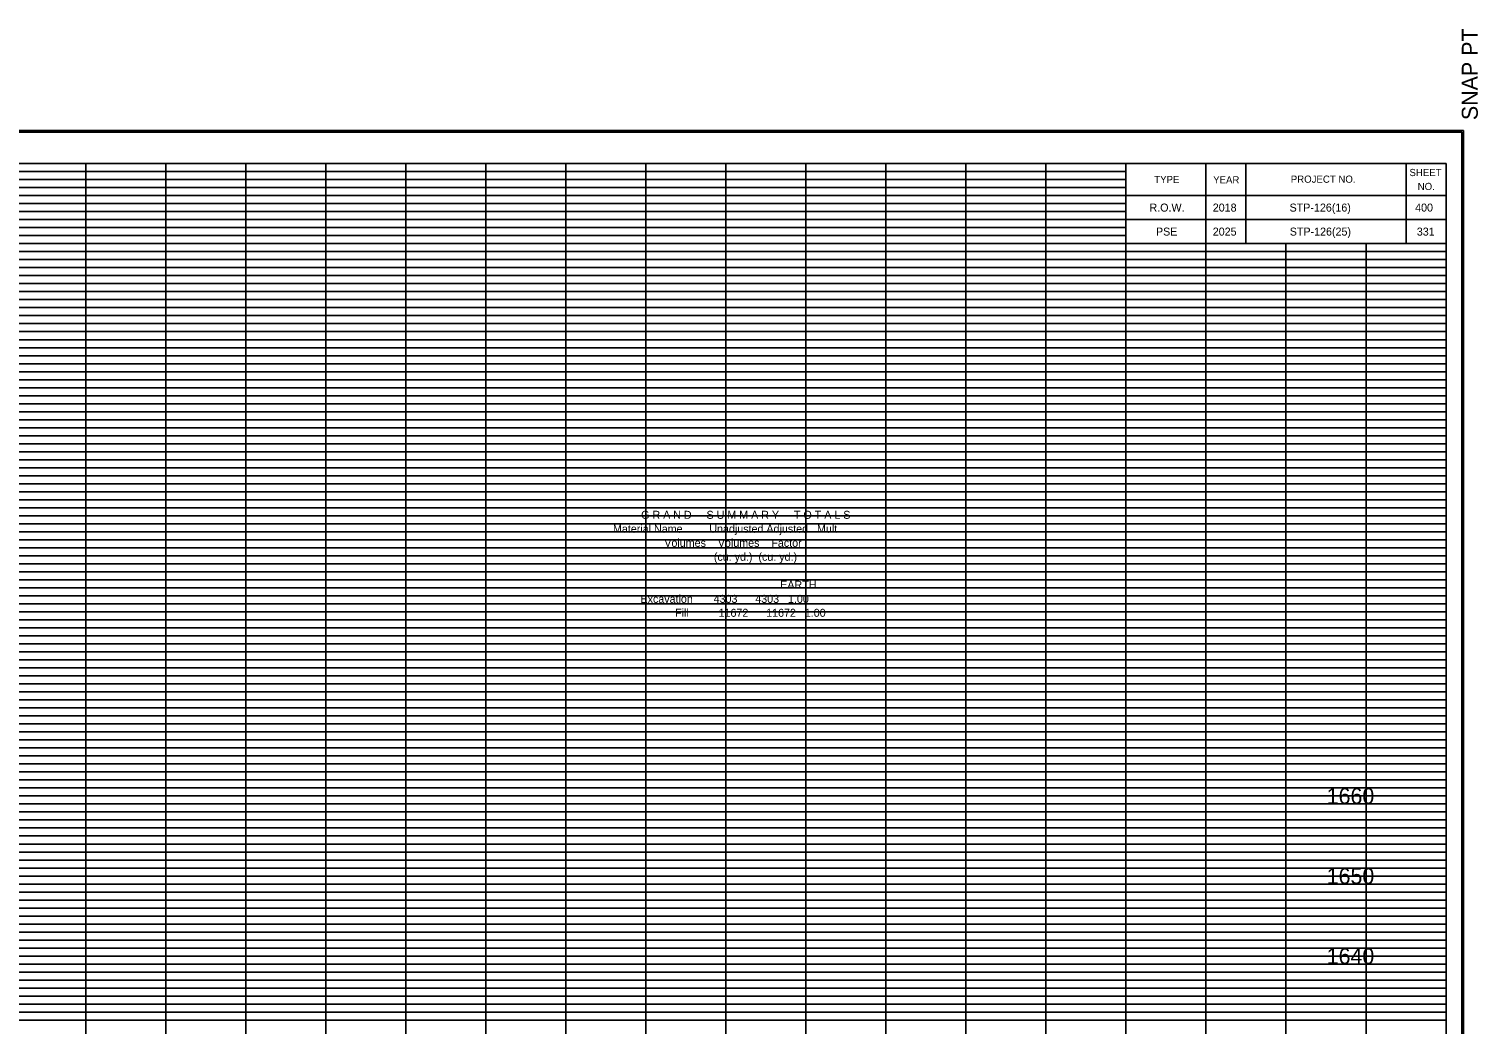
# Model space of a CAD drawing. Extents: x 955 to 1375, y 1248 to 3657.
# Drawn here: x 1142.9 to 1324, y 3532.5 to 3656.8 of the extents above; entities that cross this region are included whole.
import ezdxf

# ---------------------------------------------------------------- set-up
doc = ezdxf.new("R2010")
doc.units = 0
for name, color, linetype in [('DESIGN - SCRATCH - User 1', 7, 'Continuous'), ('DESIGN - SHEET - Corner Text', 7, 'Continuous'), ('DESIGN - SHEET - Light Grid', 7, 'Continuous'), ('DESIGN - SHEET - Linework', 7, 'Continuous'), ('DESIGN - SHEET - Plot Shape', 7, 'Continuous'), ('DESIGN - TYPICAL - Text', 7, 'Continuous'), ('DESIGN - UTILITIES - Cable (Overhead) with Text', 7, 'Continuous')]:
    doc.layers.add(name, color=color, linetype=linetype)

# ---------------------------------------------------------------- blocks, each defined once
blk = doc.blocks.new('XSTSHT')
at = {"layer": 'DESIGN - SCRATCH - User 1'}
for p, q in [((28.5, 20.45), (28.5, 20.45)), ((29.24, 20.45), (29.24, 20.45)), ((30.49, 20.45), (30.49, 20.45)), ((31.74, 20.45), (31.74, 20.45)), ((28.5, 20.15), (28.5, 20.15)), ((29.24, 20.15), (29.24, 20.15)), ((30.49, 20.15), (30.49, 20.15)), ((31.74, 20.15), (31.74, 20.15))]:
    blk.add_line(p, q, dxfattribs=at)
at = {"layer": 'DESIGN - SHEET - Light Grid'}
for p, q in [((8, 20.9), (16, 20.9)), ((16, 20.9), (24, 20.9)), ((24, 20.9), (28, 20.9)), ((8, 20.8), (16, 20.8)), ((8, 20.7), (16, 20.7)), ((16, 20.8), (24, 20.8)), ((16, 20.7), (24, 20.7)), ((24, 20.8), (28, 20.8)), ((24, 20.7), (28, 20.7)), ((8, 20.6), (16, 20.6)), ((8, 20.5), (16, 20.5)), ((16, 20.6), (24, 20.6)), ((16, 20.5), (24, 20.5)), ((24, 20.6), (28, 20.6)), ((24, 20.5), (28, 20.5)), ((8, 20.4), (16, 20.4)), ((8, 20.3), (16, 20.3)), ((16, 20.4), (24, 20.4)), ((16, 20.3), (24, 20.3)), ((24, 20.4), (28, 20.4)), ((24, 20.3), (28, 20.3)), ((8, 20.2), (16, 20.2)), ((16, 20.2), (24, 20.2)), ((24, 20.2), (28, 20.2)), ((8, 20.1), (16, 20.1)), ((16, 20.1), (24, 20.1)), ((24, 20.1), (28, 20.1)), ((8, 19.9), (16, 19.9)), ((8, 19.8), (16, 19.8)), ((16, 19.9), (24, 19.9)), ((16, 19.8), (24, 19.8)), ((24, 19.9), (32, 19.9)), ((24, 19.8), (32, 19.8)), ((8, 19.7), (16, 19.7)), ((8, 19.6), (16, 19.6)), ((16, 19.7), (24, 19.7)), ((16, 19.6), (24, 19.6)), ((24, 19.7), (32, 19.7)), ((24, 19.6), (32, 19.6)), ((8, 19.5), (16, 19.5)), ((8, 19.4), (16, 19.4)), ((16, 19.5), (24, 19.5)), ((16, 19.4), (24, 19.4)), ((24, 19.5), (32, 19.5)), ((24, 19.4), (32, 19.4)), ((8, 19.3), (16, 19.3)), ((8, 19.2), (16, 19.2)), ((16, 19.3), (24, 19.3)), ((16, 19.2), (24, 19.2)), ((24, 19.3), (32, 19.3)), ((24, 19.2), (32, 19.2)), ((8, 19.1), (16, 19.1)), ((16, 19.1), (24, 19.1)), ((24, 19.1), (32, 19.1)), ((8, 18.9), (16, 18.9)), ((16, 18.9), (24, 18.9)), ((24, 18.9), (32, 18.9)), ((8, 18.8), (16, 18.8)), ((8, 18.7), (16, 18.7)), ((16, 18.8), (24, 18.8)), ((16, 18.7), (24, 18.7)), ((24, 18.8), (32, 18.8)), ((24, 18.7), (32, 18.7)), ((8, 18.6), (16, 18.6)), ((8, 18.5), (16, 18.5)), ((16, 18.6), (24, 18.6)), ((16, 18.5), (24, 18.5)), ((24, 18.6), (32, 18.6)), ((24, 18.5), (32, 18.5)), ((8, 18.4), (16, 18.4)), ((8, 18.3), (16, 18.3)), ((16, 18.4), (24, 18.4)), ((16, 18.3), (24, 18.3)), ((24, 18.4), (32, 18.4)), ((24, 18.3), (32, 18.3)), ((8, 18.2), (16, 18.2)), ((16, 18.2), (24, 18.2)), ((24, 18.2), (32, 18.2)), ((8, 18.1), (16, 18.1)), ((16, 18.1), (24, 18.1)), ((24, 18.1), (32, 18.1)), ((8, 17.9), (16, 17.9)), ((8, 17.8), (16, 17.8)), ((16, 17.9), (24, 17.9)), ((16, 17.8), (24, 17.8)), ((24, 17.9), (32, 17.9)), ((24, 17.8), (32, 17.8)), ((8, 17.7), (16, 17.7)), ((8, 17.6), (16, 17.6)), ((16, 17.7), (24, 17.7)), ((16, 17.6), (24, 17.6)), ((24, 17.7), (32, 17.7)), ((24, 17.6), (32, 17.6)), ((8, 17.5), (16, 17.5)), ((8, 17.4), (16, 17.4)), ((16, 17.5), (24, 17.5)), ((16, 17.4), (24, 17.4)), ((24, 17.5), (32, 17.5)), ((24, 17.4), (32, 17.4)), ((8, 17.3), (16, 17.3)), ((16, 17.3), (24, 17.3)), ((24, 17.3), (32, 17.3)), ((8, 17.2), (16, 17.2)), ((8, 17.1), (16, 17.1)), ((16, 17.2), (24, 17.2)), ((16, 17.1), (24, 17.1)), ((24, 17.2), (32, 17.2)), ((24, 17.1), (32, 17.1)), ((8, 16.9), (16, 16.9)), ((16, 16.9), (24, 16.9)), ((24, 16.9), (32, 16.9)), ((8, 16.8), (16, 16.8)), ((8, 16.7), (16, 16.7)), ((16, 16.8), (24, 16.8)), ((16, 16.7), (24, 16.7)), ((24, 16.8), (32, 16.8)), ((24, 16.7), (32, 16.7)), ((8, 16.6), (16, 16.6)), ((8, 16.5), (16, 16.5)), ((16, 16.6), (24, 16.6)), ((16, 16.5), (24, 16.5)), ((24, 16.6), (32, 16.6)), ((24, 16.5), (32, 16.5)), ((8, 16.4), (16, 16.4)), ((8, 16.3), (16, 16.3)), ((16, 16.4), (24, 16.4)), ((16, 16.3), (24, 16.3)), ((24, 16.4), (32, 16.4)), ((24, 16.3), (32, 16.3)), ((8, 16.2), (16, 16.2)), ((16, 16.2), (24, 16.2)), ((24, 16.2), (32, 16.2)), ((8, 16.1), (16, 16.1)), ((16, 16.1), (24, 16.1)), ((24, 16.1), (32, 16.1)), ((8, 15.9), (16, 15.9)), ((8, 15.8), (16, 15.8)), ((16, 15.9), (24, 15.9)), ((16, 15.8), (24, 15.8)), ((24, 15.9), (32, 15.9)), ((24, 15.8), (32, 15.8)), ((8, 15.7), (16, 15.7)), ((8, 15.6), (16, 15.6)), ((16, 15.7), (24, 15.7)), ((16, 15.6), (24, 15.6)), ((24, 15.7), (32, 15.7)), ((24, 15.6), (32, 15.6)), ((8, 15.5), (16, 15.5)), ((8, 15.4), (16, 15.4)), ((16, 15.5), (24, 15.5)), ((16, 15.4), (24, 15.4)), ((24, 15.5), (32, 15.5)), ((24, 15.4), (32, 15.4)), ((8, 15.3), (16, 15.3)), ((16, 15.3), (24, 15.3)), ((24, 15.3), (32, 15.3)), ((8, 15.2), (16, 15.2)), ((8, 15.1), (16, 15.1)), ((16, 15.2), (24, 15.2)), ((16, 15.1), (24, 15.1)), ((24, 15.2), (32, 15.2)), ((24, 15.1), (32, 15.1)), ((8, 14.9), (16, 14.9)), ((16, 14.9), (24, 14.9)), ((24, 14.9), (32, 14.9)), ((8, 14.8), (16, 14.8)), ((8, 14.7), (16, 14.7)), ((16, 14.8), (24, 14.8)), ((16, 14.7), (24, 14.7)), ((24, 14.8), (32, 14.8)), ((24, 14.7), (32, 14.7)), ((8, 14.6), (16, 14.6)), ((8, 14.5), (16, 14.5)), ((16, 14.6), (24, 14.6)), ((16, 14.5), (24, 14.5)), ((24, 14.6), (32, 14.6)), ((24, 14.5), (32, 14.5)), ((8, 14.4), (16, 14.4)), ((16, 14.4), (24, 14.4)), ((24, 14.4), (32, 14.4)), ((8, 14.3), (16, 14.3)), ((8, 14.2), (16, 14.2)), ((16, 14.3), (24, 14.3)), ((16, 14.2), (24, 14.2)), ((24, 14.3), (32, 14.3)), ((24, 14.2), (32, 14.2)), ((8, 14.1), (16, 14.1)), ((16, 14.1), (24, 14.1)), ((24, 14.1), (32, 14.1)), ((8, 13.9), (16, 13.9)), ((8, 13.8), (16, 13.8)), ((16, 13.9), (24, 13.9)), ((16, 13.8), (24, 13.8)), ((24, 13.9), (32, 13.9)), ((24, 13.8), (32, 13.8)), ((8, 13.7), (16, 13.7)), ((8, 13.6), (16, 13.6)), ((16, 13.7), (24, 13.7)), ((16, 13.6), (24, 13.6)), ((24, 13.7), (32, 13.7)), ((24, 13.6), (32, 13.6)), ((8, 13.5), (16, 13.5)), ((16, 13.5), (24, 13.5)), ((24, 13.5), (32, 13.5)), ((8, 13.4), (16, 13.4)), ((8, 13.3), (16, 13.3)), ((16, 13.4), (24, 13.4)), ((16, 13.3), (24, 13.3)), ((24, 13.4), (32, 13.4)), ((24, 13.3), (32, 13.3)), ((8, 13.2), (16, 13.2)), ((8, 13.1), (16, 13.1)), ((16, 13.2), (24, 13.2)), ((16, 13.1), (24, 13.1)), ((24, 13.2), (32, 13.2)), ((24, 13.1), (32, 13.1)), ((8, 12.9), (16, 12.9)), ((16, 12.9), (24, 12.9)), ((24, 12.9), (32, 12.9)), ((8, 12.8), (16, 12.8)), ((8, 12.7), (16, 12.7)), ((16, 12.8), (24, 12.8)), ((16, 12.7), (24, 12.7)), ((24, 12.8), (32, 12.8)), ((24, 12.7), (32, 12.7)), ((8, 12.6), (16, 12.6)), ((8, 12.5), (16, 12.5)), ((16, 12.6), (24, 12.6)), ((16, 12.5), (24, 12.5)), ((24, 12.6), (32, 12.6)), ((24, 12.5), (32, 12.5)), ((8, 12.4), (16, 12.4)), ((16, 12.4), (24, 12.4)), ((24, 12.4), (32, 12.4)), ((8, 12.3), (16, 12.3)), ((8, 12.2), (16, 12.2)), ((16, 12.3), (24, 12.3)), ((16, 12.2), (24, 12.2)), ((24, 12.3), (32, 12.3)), ((24, 12.2), (32, 12.2)), ((8, 12.1), (16, 12.1)), ((16, 12.1), (24, 12.1)), ((24, 12.1), (32, 12.1)), ((8, 11.9), (16, 11.9)), ((8, 11.8), (16, 11.8)), ((16, 11.9), (24, 11.9)), ((16, 11.8), (24, 11.8)), ((24, 11.9), (32, 11.9)), ((24, 11.8), (32, 11.8)), ((8, 11.7), (16, 11.7)), ((8, 11.6), (16, 11.6)), ((16, 11.7), (24, 11.7)), ((16, 11.6), (24, 11.6)), ((24, 11.7), (32, 11.7)), ((24, 11.6), (32, 11.6)), ((8, 11.5), (16, 11.5)), ((16, 11.5), (24, 11.5)), ((24, 11.5), (32, 11.5)), ((8, 11.4), (16, 11.4)), ((8, 11.3), (16, 11.3)), ((16, 11.4), (24, 11.4)), ((16, 11.3), (24, 11.3)), ((24, 11.4), (32, 11.4)), ((24, 11.3), (32, 11.3)), ((8, 11.2), (16, 11.2)), ((8, 11.1), (16, 11.1)), ((16, 11.2), (24, 11.2)), ((16, 11.1), (24, 11.1)), ((24, 11.2), (32, 11.2)), ((24, 11.1), (32, 11.1)), ((8, 10.9), (16, 10.9)), ((16, 10.9), (24, 10.9)), ((24, 10.9), (32, 10.9)), ((8, 10.8), (16, 10.8)), ((8, 10.7), (16, 10.7)), ((16, 10.8), (24, 10.8)), ((16, 10.7), (24, 10.7)), ((24, 10.8), (32, 10.8)), ((24, 10.7), (32, 10.7)), ((8, 10.6), (16, 10.6)), ((16, 10.6), (24, 10.6)), ((24, 10.6), (32, 10.6)), ((8, 10.5), (16, 10.5)), ((8, 10.4), (16, 10.4)), ((16, 10.5), (24, 10.5)), ((16, 10.4), (24, 10.4)), ((24, 10.5), (32, 10.5)), ((24, 10.4), (32, 10.4)), ((8, 10.3), (16, 10.3)), ((16, 10.3), (24, 10.3)), ((24, 10.3), (32, 10.3))]:
    blk.add_line(p, q, dxfattribs=at)
at = {"layer": 'DESIGN - SHEET - Linework'}
for p, q in [((-1.823, 21.414), (32.217, 21.414)), ((32.217, 21.414), (32.217, -0.414)), ((15, 0), (15, 21)), ((16, 0), (16, 21)), ((17, 0), (17, 21)), ((18, 0), (18, 21)), ((19, 0), (19, 21)), ((20, 0), (20, 21)), ((21, 0), (21, 21)), ((22, 0), (22, 21)), ((23, 0), (23, 21)), ((24, 0), (24, 21)), ((25, 0), (25, 21)), ((26, 0), (26, 21)), ((27, 0), (27, 21)), ((0, 20), (28, 20)), ((28, 0), (28, 20)), ((29, 0), (29, 20)), ((30, 0), (30, 20)), ((31, 0), (31, 20)), ((0, 19), (32, 19)), ((0, 18), (32, 18)), ((0, 17), (32, 17)), ((0, 16), (32, 16)), ((0, 15), (32, 15)), ((0, 14), (32, 14)), ((0, 13), (32, 13)), ((0, 12), (32, 12)), ((0, 11), (32, 11))]:
    blk.add_line(p, q, dxfattribs=at)
for points in [[(0, 21), (0, 0), (32, 0), (32, 21), (0, 21)], [(28, 21), (28, 20), (32, 20), (32, 21), (31.5, 21), (31.5, 20), (29.5, 20), (29.5, 21), (29, 21), (29, 20), (32, 20), (28, 20), (28, 20.3), (32, 20.3), (32, 20.6), (28, 20.6)]]:
    blk.add_lwpolyline(points, dxfattribs=at)
at = {"layer": 'DESIGN - SHEET - Plot Shape'}
for points in [[(-1.803, 21.394), (32.197, 21.394), (32.197, -0.394), (-1.803, -0.394)], [(-0.85, 21), (32, 21), (32, -0.25), (-0.85, -0.25)]]:
    blk.add_lwpolyline(points, close=True, dxfattribs=at)
at = {"layer": 'DESIGN - SHEET - Corner Text'}
blk.add_text('  SNAP PT', height=0.2, rotation=90, dxfattribs=at).set_placement((32.397, 21.394))
for s, p in [('TYPE', (28.354, 20.756)), ('YEAR', (29.09, 20.752)), ('PROJECT NO.', (30.06, 20.76)), ('SHEET', (31.543, 20.843)), ('NO.', (31.646, 20.669))]:
    blk.add_text(s, height=0.09, dxfattribs=at).set_placement(p)

msp = doc.modelspace()

# ---------------------------------------------------------------- linework, layer by layer
at = {"layer": 'DESIGN - SHEET - Plot Shape'}
msp.add_lwpolyline([(991.5, 3427.5), (1320, 3427.5), (1320, 3640), (991.5, 3640)], close=True, dxfattribs=at)

# ---------------------------------------------------------------- block references
at = {"layer": 'DESIGN - UTILITIES - Cable (Overhead) with Text', "xscale": 10, "yscale": 10}
msp.add_blockref('XSTSHT', (1000, 3430), dxfattribs=at)

# ---------------------------------------------------------------- texts
at = {"layer": 'DESIGN - SHEET - Corner Text'}
for s, p in [('R.O.W.', (1282.94, 3634)), ('2018', (1290.85, 3634)), ('STP-126(16)', (1300.45, 3634)), ('400', (1316.14, 3634)), ('PSE', (1283.75, 3631)), ('2025', (1290.85, 3631)), ('STP-126(25)', (1300.47, 3631)), ('331', (1316.35, 3631))]:
    msp.add_text(s, height=1, dxfattribs=at).set_placement(p)
at = {"layer": 'DESIGN - TYPICAL - Text'}
for s, height, p in [('G R A N D     S U M M A R Y     T O T A L S', 1, (1219.41, 3595.62)), ('               Material Name         Unadjusted Adjusted   Mult', 1, (1210.32, 3593.88)), ('                                     Volumes    Volumes    Factor', 1, (1208.56, 3592.12)), ('                                     (cu. yd.)  (cu. yd.)', 1, (1214.75, 3590.38)), ('        ---------------------------- ---------- ---------- ------', 1, (1212.85, 3588.62)), ('        EARTH', 1, (1233.82, 3586.88)), ('                          Excavation       4303      4303   1.00', 1, (1209.67, 3585.12)), ('                            Fill          11672      11672   1.00', 1, (1213.26, 3583.38)), ('     1660     ', 2, (1301.37, 3560)), ('     1650     ', 2, (1301.37, 3550)), ('     1640     ', 2, (1301.37, 3540))]:
    msp.add_text(s, height=height, dxfattribs=at).set_placement(p)

doc.saveas('drawing.dxf')
